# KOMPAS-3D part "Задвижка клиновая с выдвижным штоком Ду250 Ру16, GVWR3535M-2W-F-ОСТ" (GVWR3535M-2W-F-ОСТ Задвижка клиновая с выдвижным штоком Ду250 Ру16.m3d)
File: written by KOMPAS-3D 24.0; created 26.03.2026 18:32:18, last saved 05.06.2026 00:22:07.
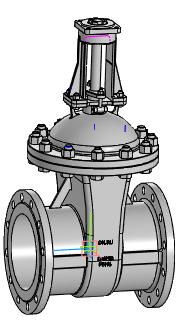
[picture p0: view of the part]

Document properties: Автор: R2D2; Полное имя файла: E:\Работа\Зайцев\GVWR3535M-2W-F-ОСТ Задвижка клиновая 30нж941нж DN.ru Ду50-200 Ру16\исходные данные\DN250\GVWR3535M-2W-F-ОСТ Задвижка клиновая с выдвижным штоком Ду250 Ру16.m3d

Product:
- Component [detail]: AS 1110 - M10 x 35  | qty 4  | pos. 2  | Комментарий: Болты и винты   шестигранные точные   метрические ISO; Автор: R2D2; additional columns: Сталь, мягкая; source file: AS 1110 - M10 x 35 AS 1110 - M10 x 35.m3d
- Component [detail]: ANSI B18.2.4.2M - M10x1,5 - 16  | designation ANSI B18.2.4.2M - M10x1,5  | qty 4  | pos. 3  | Комментарий: Типы метрических   шестигранных гаек   2; Автор: R2D2; additional columns: Сталь, мягкая; source file: ANSI B18.2.4.2M - M10x1,5 ANSI B18.2.4.2M - M10x1,5 - 16.m3d
- Component [detail]: ANSI B18.2.4.2M - M8x1,25 - 13  | designation ANSI B18.2.4.2M - M8x1,25  | qty 1  | pos. 4  | Комментарий: Типы метрических   шестигранных гаек   2; Автор: R2D2; additional columns: Сталь, мягкая; source file: ANSI B18.2.4.2M - M8x1,25 ANSI B18.2.4.2M - M8x1,25 - 13.m3d
- Component [detail]: ANSI B18.2.4.2M - M20x2,5 - 30  | designation ANSI B18.2.4.2M - M20x2,5  | qty 12  | pos. 5  | Комментарий: Типы метрических   шестигранных гаек   2; Автор: R2D2; additional columns: Сталь, мягкая; source file: ANSI B18.2.4.2M - M20x2,5 ANSI B18.2.4.2M - M20x2,5 - 30.m3d
- Component [detail]: AS 1110 - M20 x 70  | qty 12  | pos. 6  | Комментарий: Болты и винты   шестигранные точные   метрические ISO; Автор: R2D2; additional columns: Сталь, мягкая; source file: AS 1110 - M20 x 70 AS 1110 - M20 x 70.m3d
- Component [detail]: Деталь1  | qty 1  | pos. 7  | Автор: R2D2; additional columns: Типовые; source file: 2.m3d
- Component [detail]: ANSI B18.2.4.2M - M8x1,25 - 13  | designation ANSI B18.2.4.2M - M8x1,25-01  | qty 1  | pos. 8  | Комментарий: Типы метрических   шестигранных гаек   2; Автор: R2D2; additional columns: Сталь, мягкая; source file: ANSI B18.2.4.2M - M8x1,25 ANSI B18.2.4.2M - M8x1,25 - 13.m3d
- Component [detail]: Фланец  | qty 2  | pos. 7  | Автор: R2D2; additional columns: Типовые; source file: Фланец DN250 Pn16 b30.m3d
- Component [detail]: DN250_3D_STEP  | designation Сборка  | qty 1  | pos. 9  | Масса: 5.389074; Автор: R2D2; source file: Фланец Б.m3d
- Body: Тело 1  | qty 1
    Масса: 320.314747
- Body: Тело 2  | qty 1
    Масса: 320.314747
- Part/product: Задвижка клиновая с выдвижным штоком Ду250 Ру16  | designation GVWR3535M-2W-F-ОСТ
    Масса: 142.5
    Раздел спецификации: Прочие изделия
    Примечание: D040-09831

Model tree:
1. Массив по концентрической сетке:1  (labels: Грань.Твердое тело1)  (12 pattern instances)
     Шаг 2 = 360
2. Массив по сетке:1  (labels: Грань.Твердое тело1)  (4 pattern instances)
     Шаг 1 = 50; Угол раствора = 90; Шаг 2 = 120
3. Масштабирование:1
4. Масштабирование : Твердое тело1
5. Масштабирование : Solid1
6. Масштабирование : Ребро.Solid1  (with: Масштабирование : Solid1)  (labels: Твердое тело1; Solid1; Ребро.Solid1)
     Масштаб по оси Х = 1; Масштаб по оси Y = 1; Масштаб по оси Z = 1; Коэффициент = 1.25
7. Элемент выдавливания:1  (with: Грань.Элемент выдавливания:2, Грань.Элемент вращения:1)
     Расстояние 1 = 29.4956
8. Элемент выдавливания:2  (with: Грань.Элемент выдавливания:1, Грань.Элемент вращения:1)
     Расстояние 1 = 38.0521
9. Скругление:1  (with: Ребро.Элемент выдавливания:2, Ребро.Элемент выдавливания:1)
     Радиус = 10
10. Элемент выдавливания:3  (with: Грань.Элемент выдавливания:1)
     Расстояние 1 = 70
11. Эскиз:1  (with: Вершина.Элемент выдавливания:3)
12. Элемент по траектории:1  (with: Грань.Элемент выдавливания:3)
     Толщина стенки 1 = 1; Длина траектории = 115.416
13. Элемент выдавливания:4  (with: Грань.Элемент выдавливания:1, Грань.Элемент по траектории:1)
     Расстояние 1 = 141.883
14. Эскиз:2
15. Элемент выдавливания:5  (with: Грань.Элемент выдавливания:1, Грань.Элемент вращения:1, Грань.Элемент выдавливания:5, Грань.Элемент выдавливания:7)  (labels: Грань.Твердое тело1; Грань.Solid1; Solid1; Твердое тело1)
     Расстояние 1 = 157.25; Смещение 1 = 1; Ориентация = 2; Расстояние = -225; Ориентация = 2; Расстояние = -767

Referenced files in E:\Работа\Зайцев\GVWR3535M-2W-F-ОСТ Задвижка клиновая 30нж941нж DN.ru Ду50-200 Ру16\исходные данные\DN250\: AS 1110 - M10 x 35 AS 1110 - M10 x 35.m3d, ANSI B18.2.4.2M - M10x1,5 ANSI B18.2.4.2M - M10x1,5 - 16.m3d, ANSI B18.2.4.2M - M8x1,25 ANSI B18.2.4.2M - M8x1,25 - 13.m3d, ANSI B18.2.4.2M - M20x2,5 ANSI B18.2.4.2M - M20x2,5 - 30.m3d, AS 1110 - M20 x 70 AS 1110 - M20 x 70.m3d, 2.m3d, Фланец DN250 Pn16 b30.m3d, Фланец Б.m3d
Referenced files in E:\Работа\Зайцев\GVWR3131M-2W-F-S Задвижка клиновая с выдвижным штоком DN.ru Ду50-200 Ру63\DN200\исходные материалы\: ANSI B18.2.4.2M - M20x2,5 ANSI B18.2.4.2M - M20x2,5 - 30.m3d, AS 1110 - M20 x 70 AS 1110 - M20 x 70.m3d, ANSI B18.2.4.2M - M10x1,5 ANSI B18.2.4.2M - M10x1,5 - 16.m3d, AS 1110 - M10 x 35 AS 1110 - M10 x 35.m3d
Referenced files in E:\Работа\Зайцев\GVWR2626M-2W-F-S Задвижка клиновая с выдвижным штоком DN.ru Ду50-300 Ру16\DN250\исходные материалы\: Фланец DN250 Pn16 b30.m3d
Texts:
  GVWR3535M-2W-F-ОСТ
  DN250
  GOST 26.020 Pr3
  PN16
  AS 1110 - M10 x 35 AS 1110 - M10 x 35 (1)
  ANSI B18.2.4.2M - M10x1,5 ANSI B18.2.4.2M - M10x1,5 - 16 (1)
  ANSI B18.2.4.2M - M8x1,25 ANSI B18.2.4.2M - M8x1,25 - 13
  ANSI B18.2.4.2M - M20x2,5 ANSI B18.2.4.2M - M20x2,5 - 30 (1)
  AS 1110 - M20 x 70 AS 1110 - M20 x 70 (1)
  Деталь1 Деталь1
  ANSI B18.2.4.2M - M20x2,5 ANSI B18.2.4.2M - M20x2,5 - 30 (2)
  AS 1110 - M20 x 70 AS 1110 - M20 x 70 (2)
  ANSI B18.2.4.2M - M20x2,5 ANSI B18.2.4.2M - M20x2,5 - 30 (3)
  AS 1110 - M20 x 70 AS 1110 - M20 x 70 (3)
  ANSI B18.2.4.2M - M20x2,5 ANSI B18.2.4.2M - M20x2,5 - 30 (4)
  AS 1110 - M20 x 70 AS 1110 - M20 x 70 (4)
  ANSI B18.2.4.2M - M20x2,5 ANSI B18.2.4.2M - M20x2,5 - 30 (5)
  AS 1110 - M20 x 70 AS 1110 - M20 x 70 (5)
  ANSI B18.2.4.2M - M20x2,5 ANSI B18.2.4.2M - M20x2,5 - 30 (6)
  AS 1110 - M20 x 70 AS 1110 - M20 x 70 (6)
  ANSI B18.2.4.2M - M20x2,5 ANSI B18.2.4.2M - M20x2,5 - 30 (7)
  AS 1110 - M20 x 70 AS 1110 - M20 x 70 (7)
  ANSI B18.2.4.2M - M20x2,5 ANSI B18.2.4.2M - M20x2,5 - 30 (8)
  AS 1110 - M20 x 70 AS 1110 - M20 x 70 (8)
  ANSI B18.2.4.2M - M20x2,5 ANSI B18.2.4.2M - M20x2,5 - 30 (9)
  AS 1110 - M20 x 70 AS 1110 - M20 x 70 (9)
  ANSI B18.2.4.2M - M20x2,5 ANSI B18.2.4.2M - M20x2,5 - 30 (10)
  AS 1110 - M20 x 70 AS 1110 - M20 x 70 (10)
  ANSI B18.2.4.2M - M20x2,5 ANSI B18.2.4.2M - M20x2,5 - 30 (11)
  AS 1110 - M20 x 70 AS 1110 - M20 x 70 (11)
  ANSI B18.2.4.2M - M20x2,5 ANSI B18.2.4.2M - M20x2,5 - 30 (12)
  AS 1110 - M20 x 70 AS 1110 - M20 x 70 (12)
  ANSI B18.2.4.2M - M10x1,5 ANSI B18.2.4.2M - M10x1,5 - 16 (2)
  AS 1110 - M10 x 35 AS 1110 - M10 x 35 (2)
  ANSI B18.2.4.2M - M10x1,5 ANSI B18.2.4.2M - M10x1,5 - 16 (3)
  AS 1110 - M10 x 35 AS 1110 - M10 x 35 (3)
  ANSI B18.2.4.2M - M10x1,5 ANSI B18.2.4.2M - M10x1,5 - 16 (4)
  AS 1110 - M10 x 35 AS 1110 - M10 x 35 (4)
  ANSI B18.2.4.2M - M8x1,25-01 ANSI B18.2.4.2M - M8x1,25 - 13
  Фланец (1)
  Фланец (2)
  Сборка DN250_3D_STEP
  Ось Y.Начало координат
  Ось Z.Начало координат
  Плоскость ZY.Начало координат
  Плоскость ZX.Начало координат
  Плоскость XY.Начало координат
